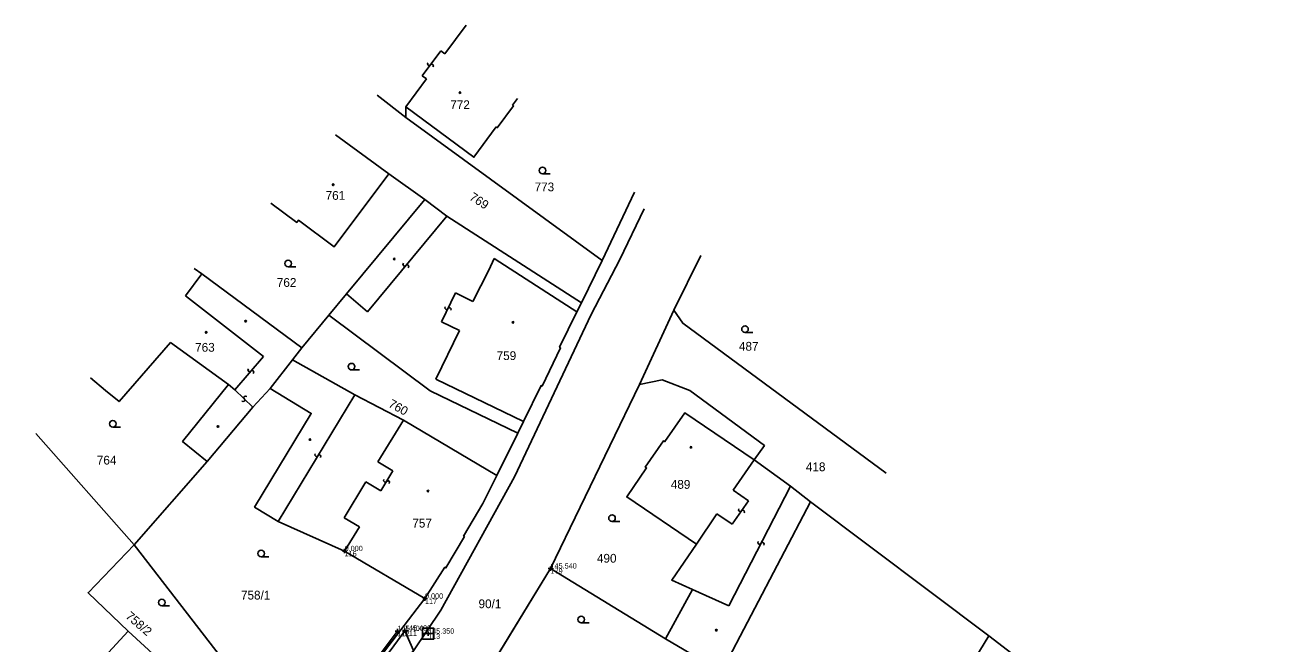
# Model space of a CAD drawing. Extents: x -748509 to -748117, y -967868 to -967533.
# Drawn here: x -748315.7 to -748173.1, y -967603.9 to -967533.4 of the extents above; entities that cross this region are included whole.
import ezdxf

# ---------------------------------------------------------------- set-up
doc = ezdxf.new("R2010")
doc.units = 0
for name, color, linetype in [('Body polohopisu', 7, 'Continuous'), ('Budovy', 7, 'Continuous'), ('KM', 7, 'Continuous'), ('Ploty_opěrné zdi', 7, 'Continuous'), ('Rozhraní ploch', 7, 'Continuous'), ('Vnitřní kresba', 7, 'Continuous'), ('Výšky bodů', 7, 'Continuous'), ('Značky IS', 7, 'Continuous'), ('Čísla bodů', 7, 'Continuous')]:
    doc.layers.add(name, color=color, linetype=linetype)

msp = doc.modelspace()

# ---------------------------------------------------------------- linework, layer by layer
at = {"layer": 'Body polohopisu'}
for p, q in [((-748279.32, -967593.32), (-748279.57, -967593.32)), ((-748279.32, -967593.32), (-748279.32, -967593.07)), ((-748279.32, -967593.32), (-748279.07, -967593.32)), ((-748279.32, -967593.32), (-748279.32, -967593.57)), ((-748255.88, -967595.31), (-748256.13, -967595.31)), ((-748255.88, -967595.31), (-748255.88, -967595.06)), ((-748255.88, -967595.31), (-748255.63, -967595.31)), ((-748255.88, -967595.31), (-748255.88, -967595.56)), ((-748270.17, -967598.74), (-748270.17, -967598.49)), ((-748270.17, -967598.74), (-748270.42, -967598.74)), ((-748270.17, -967598.74), (-748269.92, -967598.74)), ((-748270.17, -967598.74), (-748270.17, -967598.99)), ((-748273.3, -967602.43), (-748273.55, -967602.43)), ((-748273.3, -967602.43), (-748273.3, -967602.18)), ((-748273.3, -967602.43), (-748273.05, -967602.43)), ((-748273.3, -967602.43), (-748273.3, -967602.68)), ((-748272.46, -967602.39), (-748272.71, -967602.39)), ((-748272.46, -967602.39), (-748272.46, -967602.14)), ((-748272.46, -967602.39), (-748272.21, -967602.39)), ((-748272.46, -967602.39), (-748272.46, -967602.64)), ((-748269.82, -967602.73), (-748270.07, -967602.73)), ((-748269.82, -967602.73), (-748269.82, -967602.48)), ((-748269.82, -967602.73), (-748269.57, -967602.73)), ((-748269.82, -967602.73), (-748269.82, -967602.98))]:
    msp.add_line(p, q, dxfattribs=at)
at = {"layer": 'Budovy'}
msp.add_lwpolyline([(-748279.32, -967593.32), (-748270.17, -967598.74)], dxfattribs=at)
at = {"layer": 'KM'}
for p, q in [((-748249.98, -967560.22), (-748272.35, -967543.89)), ((-748274.27, -967550.32), (-748280.37, -967545.9)), ((-748270.19, -967553.26), (-748274.27, -967550.32)), ((-748256.78, -967550.32), (-748255.91, -967550.32)), ((-748249.98, -967560.22), (-748246.3, -967552.43)), ((-748241.83, -967565.88), (-748238.75, -967559.62)), ((-748285.75, -967560.91), (-748284.88, -967560.91)), ((-748252.36, -967565.02), (-748249.98, -967560.22)), ((-748281.1, -967566.42), (-748284.17, -967570.14)), ((-748241.83, -967565.88), (-748245.73, -967574.34)), ((-748233.73, -967568.42), (-748232.85, -967568.42)), ((-748284.17, -967570.14), (-748285.24, -967571.52)), ((-748285.24, -967571.52), (-748287.79, -967574.8)), ((-748278.52, -967572.68), (-748277.64, -967572.68)), ((-748255.88, -967595.31), (-748245.73, -967574.34)), ((-748303.27, -967592.59), (-748314.49, -967579.92)), ((-748305.71, -967579.19), (-748304.83, -967579.19)), ((-748262, -967584.72), (-748259.59, -967579.9)), ((-748294.98, -967583.1), (-748303.27, -967592.59)), ((-748236.4, -967607.09), (-748226.27, -967587.7)), ((-748226.27, -967587.7), (-748205.97, -967602.97)), ((-748248.87, -967589.96), (-748247.99, -967589.96)), ((-748303.27, -967592.59), (-748284.33, -967617.15)), ((-748288.83, -967593.97), (-748287.95, -967593.97)), ((-748268.12, -967615.41), (-748255.88, -967595.31)), ((-748255.88, -967595.31), (-748242.78, -967603.32)), ((-748300.13, -967599.56), (-748299.25, -967599.56)), ((-748270.17, -967598.74), (-748284.33, -967617.15)), ((-748285.77, -967619.07), (-748303.96, -967602.45)), ((-748252.37, -967601.5), (-748251.49, -967601.5)), ((-748242.78, -967603.32), (-748236.4, -967607.09)), ((-748220.09, -967626.24), (-748205.97, -967602.97))]:
    msp.add_line(p, q, dxfattribs=at)
for points in [[(-748272.35, -967543.89), (-748275.62, -967541.37)], [(-748272.35, -967543.89), (-748272.36, -967542.68), (-748264.59, -967548.43), (-748262.05, -967544.99), (-748261.93, -967545.08), (-748260.08, -967542.58), (-748260.2, -967542.49), (-748259.65, -967541.74)], [(-748287.7, -967553.68), (-748284.76, -967555.87), (-748284.56, -967555.6), (-748280.49, -967558.64), (-748274.27, -967550.32)], [(-748270.19, -967553.26), (-748279.11, -967564.02), (-748281.1, -967566.42)], [(-748252.36, -967565.02), (-748267.67, -967555.14), (-748270.19, -967553.26)], [(-748245.23, -967554.32), (-748248, -967560.09), (-748251.25, -967566.35), (-748259.98, -967584.86), (-748268.35, -967600.05), (-748271.49, -967604.68), (-748279.6, -967616.66), (-748283.52, -967622.09), (-748309.26, -967655.94), (-748313.11, -967660.69), (-748315.81, -967663.73), (-748339.38, -967691.21), (-748366.68, -967719.8), (-748398.22, -967751.73), (-748421.72, -967775.27), (-748446.6, -967799.82), (-748468.93, -967821.53), (-748491.86, -967845.1), (-748500.53, -967854.44)], [(-748296.44, -967561.1), (-748295.57, -967561.73), (-748284.17, -967570.14)], [(-748259.59, -967579.9), (-748258.94, -967578.57), (-748256.95, -967574.46), (-748256.84, -967574.51), (-748254.73, -967570.16), (-748254.84, -967570.1), (-748252.87, -967566.05), (-748252.36, -967565.02)], [(-748281.1, -967566.42), (-748269.57, -967575.06), (-748259.59, -967579.9)], [(-748217.66, -967584.44), (-748240.82, -967567.36), (-748241.83, -967565.88)], [(-748308.26, -967573.59), (-748306.54, -967575.01), (-748304.99, -967576.28), (-748299.13, -967569.56), (-748292.53, -967574.34), (-748297.77, -967580.82), (-748294.98, -967583.1)], [(-748262, -967584.72), (-748272.6, -967578.41), (-748278.17, -967575.52), (-748285.24, -967571.52)], [(-748245.73, -967574.34), (-748243.17, -967573.81), (-748240.02, -967575.03), (-748231.52, -967581.29), (-748232.68, -967582.92)], [(-748287.79, -967574.8), (-748289.76, -967576.93), (-748294.98, -967583.1)], [(-748287.79, -967574.8), (-748283.11, -967577.63), (-748289.57, -967588.31), (-748286.88, -967589.93), (-748279.32, -967593.32), (-748270.17, -967598.74)], [(-748232.68, -967582.92), (-748240.58, -967577.55), (-748242.85, -967580.84), (-748243, -967580.74), (-748245.08, -967583.75), (-748244.93, -967583.85), (-748247.2, -967587.15), (-748239.26, -967592.52), (-748242.08, -967596.63), (-748239.7, -967597.71), (-748242.78, -967603.32)], [(-748232.68, -967582.92), (-748228.54, -967585.91), (-748226.27, -967587.7)], [(-748270.17, -967598.74), (-748267.89, -967595.17), (-748267.79, -967595.24), (-748265.68, -967591.67), (-748265.78, -967591.61), (-748263.59, -967587.9), (-748262, -967584.72)], [(-748303.96, -967602.45), (-748308.53, -967598.06), (-748303.27, -967592.59)], [(-748303.96, -967602.45), (-748311.58, -967610.73), (-748331.56, -967597.63)], [(-748205.97, -967602.97), (-748176.02, -967626), (-748173.05, -967628.31)]]:
    msp.add_lwpolyline(points, dxfattribs=at)
for centre, radius in [((-748266.17, -967541.07), 0.0875), ((-748256.78, -967549.94), 0.375), ((-748280.62, -967551.57), 0.0875), ((-748273.67, -967560.03), 0.0875), ((-748285.75, -967560.54), 0.375), ((-748290.59, -967567.12), 0.0875), ((-748295.08, -967568.4), 0.0875), ((-748260.15, -967567.26), 0.0875), ((-748233.73, -967568.04), 0.375), ((-748278.52, -967572.3), 0.375), ((-748305.71, -967578.81), 0.375), ((-748293.74, -967579.12), 0.0875), ((-748283.26, -967580.61), 0.0875), ((-748239.87, -967581.49), 0.0875), ((-748269.83, -967586.48), 0.0875), ((-748248.87, -967589.58), 0.375), ((-748288.83, -967593.59), 0.375), ((-748300.13, -967599.18), 0.375), ((-748252.37, -967601.12), 0.375), ((-748236.99, -967602.33), 0.0875)]:
    msp.add_circle(centre, radius, dxfattribs=at)
at = {"layer": 'Ploty_opěrné zdi'}
for points in [[(-748259.68, -967621.36), (-748266.97, -967616.31), (-748268.12, -967615.41), (-748255.88, -967595.31)], [(-748285.77, -967619.07), (-748281.16, -967612.9), (-748273.3, -967602.43)]]:
    msp.add_lwpolyline(points, dxfattribs=at)
at = {"layer": 'Rozhraní ploch'}
for points in [[(-748318.15, -967663.66), (-748318.74, -967664.07), (-748320.08, -967663.63), (-748320.81, -967664.8), (-748317.31, -967664.84), (-748311.17, -967658.18), (-748308.97, -967655.34), (-748295.87, -967638.09), (-748283.23, -967621.44), (-748271.46, -967604.65), (-748272.46, -967602.39)], [(-748272.46, -967602.39), (-748280.73, -967613.68), (-748285.31, -967619.83), (-748286.47, -967622.14), (-748292.61, -967630.26), (-748297.64, -967636.89), (-748299.99, -967634.86)]]:
    msp.add_lwpolyline(points, dxfattribs=at)
at = {"layer": 'Vnitřní kresba'}
for p, q in [((-748265.49, -967533.37), (-748267.91, -967536.65)), ((-748268.37, -967536.31), (-748270.47, -967539.16)), ((-748267.91, -967536.65), (-748268.37, -967536.31)), ((-748270.01, -967539.49), (-748272.36, -967542.68)), ((-748270.47, -967539.16), (-748270.01, -967539.49)), ((-748276.73, -967566.05), (-748267.67, -967555.14)), ((-748262.29, -967559.96), (-748262.9, -967561.29)), ((-748256.28, -967563.85), (-748262.29, -967559.96)), ((-748262.9, -967561.29), (-748264.73, -967564.86)), ((-748295.57, -967561.73), (-748297.44, -967564.23)), ((-748297.44, -967564.23), (-748288.56, -967571.14)), ((-748279.11, -967564.02), (-748276.73, -967566.05)), ((-748266.68, -967563.88), (-748268.28, -967567.21)), ((-748264.73, -967564.86), (-748266.68, -967563.88)), ((-748252.87, -967566.05), (-748256.28, -967563.85)), ((-748266.23, -967568.2), (-748268.92, -967573.73)), ((-748268.28, -967567.21), (-748266.23, -967568.2)), ((-748288.56, -967571.14), (-748291.8, -967574.93)), ((-748268.92, -967573.73), (-748258.94, -967578.57)), ((-748291.8, -967574.93), (-748292.53, -967574.34)), ((-748291.8, -967574.93), (-748289.76, -967576.93)), ((-748286.88, -967589.93), (-748278.17, -967575.52)), ((-748275.52, -967583.15), (-748272.6, -967578.41)), ((-748273.81, -967584.18), (-748275.52, -967583.15)), ((-748275.18, -967586.45), (-748273.81, -967584.18)), ((-748235.08, -967586.39), (-748232.68, -967582.92)), ((-748279.35, -967589.52), (-748276.91, -967585.41)), ((-748276.91, -967585.41), (-748275.18, -967586.45)), ((-748235.59, -967599.57), (-748228.54, -967585.91)), ((-748233.34, -967587.58), (-748235.08, -967586.39)), ((-748235.19, -967590.25), (-748233.34, -967587.58)), ((-748277.62, -967590.55), (-748279.35, -967589.52)), ((-748239.26, -967592.52), (-748236.92, -967589.06)), ((-748236.92, -967589.06), (-748235.19, -967590.25)), ((-748279.32, -967593.32), (-748277.62, -967590.55)), ((-748239.7, -967597.71), (-748235.59, -967599.57))]:
    msp.add_line(p, q, dxfattribs=at)
for points in [[(-748269.83, -967537.66), (-748269.88, -967537.81), (-748269.79, -967537.95), (-748269.64, -967537.98), (-748269.43, -967537.83), (-748269.28, -967537.87), (-748269.21, -967538.01), (-748269.26, -967538.15)], [(-748272.62, -967560.51), (-748272.68, -967560.66), (-748272.59, -967560.8), (-748272.45, -967560.84), (-748272.23, -967560.71), (-748272.08, -967560.75), (-748272.01, -967560.9), (-748272.07, -967561.03)], [(-748267.22, -967565.86), (-748267.2, -967565.71), (-748267.31, -967565.59), (-748267.46, -967565.59), (-748267.64, -967565.77), (-748267.8, -967565.76), (-748267.9, -967565.64), (-748267.87, -967565.49)], [(-748290.26, -967572.55), (-748290.32, -967572.69), (-748290.24, -967572.84), (-748290.09, -967572.87), (-748289.87, -967572.75), (-748289.72, -967572.79), (-748289.66, -967572.94), (-748289.72, -967573.07)], [(-748291.02, -967576.22), (-748290.88, -967576.29), (-748290.73, -967576.22), (-748290.68, -967576.07), (-748290.8, -967575.84), (-748290.74, -967575.7), (-748290.59, -967575.65), (-748290.46, -967575.72)], [(-748282.67, -967582.23), (-748282.7, -967582.39), (-748282.6, -967582.52), (-748282.45, -967582.53), (-748282.25, -967582.37), (-748282.1, -967582.39), (-748282.01, -967582.52), (-748282.05, -967582.67)], [(-748274.23, -967585.6), (-748274.19, -967585.44), (-748274.29, -967585.31), (-748274.45, -967585.3), (-748274.64, -967585.46), (-748274.79, -967585.44), (-748274.88, -967585.31), (-748274.84, -967585.17)], [(-748234.43, -967588.5), (-748234.48, -967588.65), (-748234.38, -967588.79), (-748234.23, -967588.8), (-748234.02, -967588.66), (-748233.88, -967588.69), (-748233.8, -967588.83), (-748233.84, -967588.96)], [(-748231.59, -967592.63), (-748231.56, -967592.48), (-748231.67, -967592.35), (-748231.83, -967592.35), (-748232.01, -967592.53), (-748232.16, -967592.52), (-748232.26, -967592.39), (-748232.23, -967592.24)]]:
    msp.add_lwpolyline(points, dxfattribs=at)
at = {"layer": 'Značky IS'}
msp.add_line((-748270.45, -967602.73), (-748269.2, -967602.73), dxfattribs=at)
msp.add_lwpolyline([(-748270.45, -967603.36), (-748269.19, -967603.36), (-748269.19, -967602.1), (-748270.45, -967602.1)], close=True, dxfattribs=at)

# ---------------------------------------------------------------- texts
at = {"layer": 'KM'}
for s, p in [('772', (-748267.29, -967542.95)), ('773', (-748257.69, -967552.32)), ('761', (-748281.48, -967553.29)), ('762', (-748287.04, -967563.21)), ('763', (-748296.34, -967570.6)), ('487', (-748234.42, -967570.48)), ('759', (-748262.01, -967571.55)), ('764', (-748307.53, -967583.46)), ('418', (-748226.8, -967584.22)), ('489', (-748242.18, -967586.22)), ('757', (-748271.61, -967590.64)), ('490', (-748250.59, -967594.64)), ('758/1', (-748291.12, -967598.84)), ('90/1', (-748264.07, -967599.83))]:
    msp.add_text(s, height=1, dxfattribs=at).set_placement(p)
for s, rotation, p in [('769', 327, (-748265.2, -967553.21)), ('760', 331, (-748274.41, -967576.83)), ('758/2', 319, (-748304.33, -967600.87))]:
    msp.add_text(s, height=1, rotation=rotation, dxfattribs=at).set_placement(p)
at = {"layer": 'Výšky bodů'}
for s, p in [('0.000', (-748279.32, -967593.32)), ('145.540', (-748255.88, -967595.31)), ('0.000', (-748270.17, -967598.74)), ('145.400', (-748273.3, -967602.43)), ('145.400', (-748272.46, -967602.39)), ('145.350', (-748269.82, -967602.73))]:
    msp.add_text(s, height=0.6, dxfattribs=at).set_placement(p)
at = {"layer": 'Čísla bodů'}
for s, p in [('116', (-748279.32, -967593.92)), ('179', (-748255.88, -967595.91)), ('117', (-748270.17, -967599.34)), ('112', (-748273.3, -967603.03)), ('111', (-748272.46, -967602.99)), ('113', (-748269.82, -967603.33))]:
    msp.add_text(s, height=0.6, dxfattribs=at).set_placement(p)

doc.saveas('drawing.dxf')
